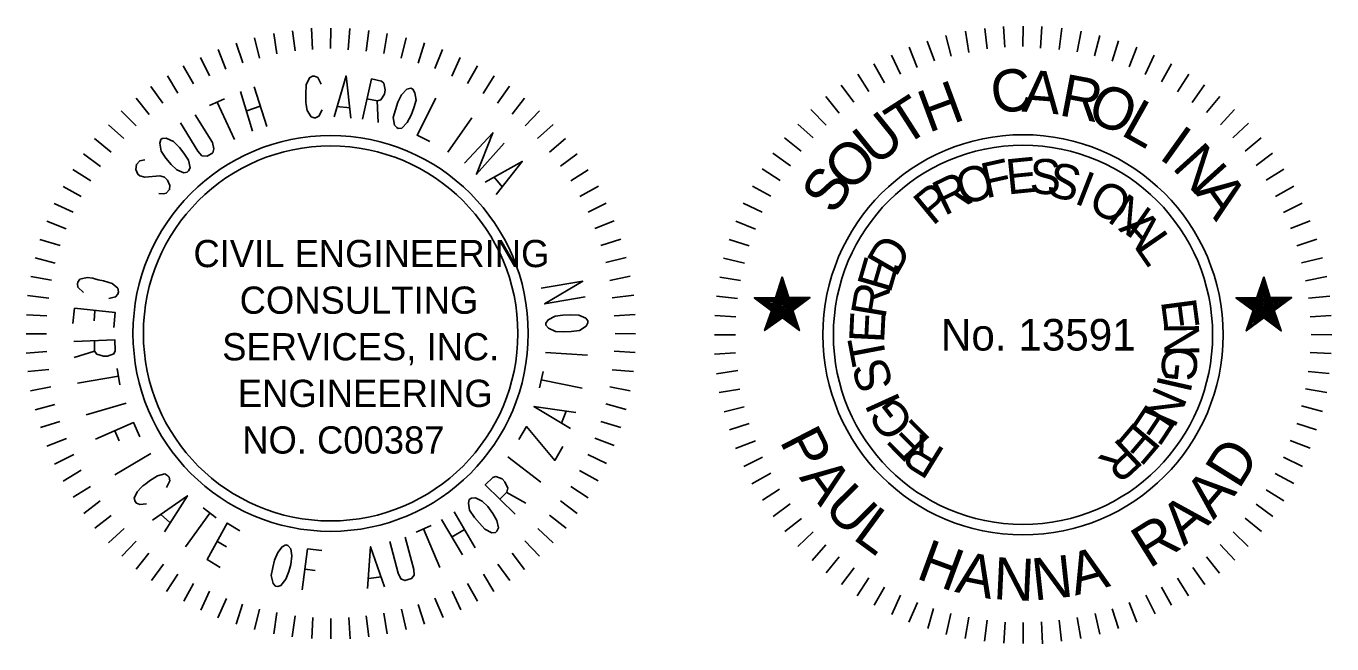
# Model space of a CAD drawing. Extents: x 116 to 2310, y 9 to 1131.
# Drawn here: x 1822.2 to 2001.5, y 103.4 to 188.2 of the extents above; entities that cross this region are included whole.
import ezdxf

# ---------------------------------------------------------------- set-up
doc = ezdxf.new("R2010")
doc.units = 0
doc.layers.add('RD_SHT_SEAL_PR', color=7, linetype='Continuous')

msp = doc.modelspace()

# ---------------------------------------------------------------- linework, layer by layer
at = {"layer": 'RD_SHT_SEAL_PR'}
for p, q in [((1853.53, 186.65), (1854.23, 183.85)), ((1856.18, 187.25), (1856.63, 184.45)), ((1858.78, 187.6), (1859.13, 184.85)), ((1861.38, 187.95), (1861.53, 185.05)), ((1864.03, 187.95), (1863.98, 185.15)), ((1866.63, 187.9), (1866.43, 185)), ((1869.23, 187.65), (1868.88, 184.8)), ((1871.78, 187.25), (1871.33, 184.5)), ((1874.38, 186.65), (1873.68, 183.85)), ((1948.48, 186.95), (1949.24, 184.13)), ((1951.18, 187.53), (1951.67, 184.62)), ((1953.83, 187.92), (1954.15, 185.1)), ((1956.42, 188.19), (1956.58, 185.33)), ((1959.12, 188.24), (1959.07, 185.43)), ((1961.66, 188.18), (1961.5, 185.22)), ((1964.42, 187.97), (1964.04, 185.05)), ((1967.06, 187.54), (1966.52, 184.73)), ((1969.65, 186.95), (1968.9, 184.14)), ((1848.58, 185.05), (1849.63, 182.35)), ((1851.03, 185.9), (1851.93, 183.2)), ((1876.88, 185.95), (1876.03, 183.15)), ((1879.38, 185.05), (1878.33, 182.4)), ((1943.46, 185.33), (1944.54, 182.57)), ((1945.94, 186.19), (1946.92, 183.49)), ((1972.19, 186.24), (1971.32, 183.43)), ((1974.73, 185.33), (1973.65, 182.63)), ((1846.13, 183.95), (1847.38, 181.4)), ((1881.78, 183.95), (1880.63, 181.35)), ((1938.6, 183.06), (1940.06, 180.46)), ((1941.03, 184.24), (1942.27, 181.65)), ((1977.1, 184.24), (1975.86, 181.6)), ((1979.48, 183.06), (1978.13, 180.57)), ((1841.58, 181.4), (1843.03, 179.05)), ((1843.73, 182.8), (1845.18, 180.3)), ((1884.18, 182.8), (1882.78, 180.35)), ((1886.48, 181.4), (1884.93, 179)), ((1936.39, 181.65), (1937.9, 179.28)), ((1981.86, 181.65), (1980.29, 179.22)), ((1839.33, 179.95), (1840.98, 177.65)), ((1888.58, 180), (1886.93, 177.65)), ((1934.12, 180.14), (1935.85, 177.82)), ((1984.02, 180.19), (1982.34, 177.76)), ((1837.28, 178.35), (1839.08, 176.1)), ((1890.63, 178.35), (1888.93, 176.15)), ((1932.02, 178.57), (1933.85, 176.3)), ((1986.12, 178.58), (1984.29, 176.36)), ((1835.23, 176.6), (1837.28, 174.55)), ((1892.68, 176.61), (1890.73, 174.55)), ((1929.96, 176.79), (1932.07, 174.63)), ((1988.12, 176.79), (1986.23, 174.68)), ((1833.48, 174.7), (1835.58, 172.8)), ((1894.58, 174.75), (1892.43, 172.8)), ((1928.18, 174.79), (1930.29, 172.9)), ((1990.06, 174.9), (1987.9, 172.9)), ((1831.59, 172.8), (1833.88, 170.95)), ((1896.28, 172.8), (1894.08, 170.95)), ((1926.34, 172.9), (1928.62, 171.07)), ((1991.79, 172.9), (1989.58, 171.07)), ((1830.08, 170.7), (1832.38, 168.95)), ((1897.88, 170.7), (1895.58, 169)), ((1924.72, 170.8), (1927.15, 169.07)), ((1993.36, 170.8), (1991.09, 169.12)), ((1923.27, 168.64), (1925.75, 167.02)), ((1994.92, 168.58), (1992.49, 167.07)), ((1828.58, 168.55), (1831.08, 167)), ((1899.38, 168.5), (1896.98, 167)), ((1827.28, 166.2), (1829.73, 164.85)), ((1900.78, 166.25), (1898.23, 164.85)), ((1921.92, 166.26), (1924.45, 164.91)), ((1996.27, 166.26), (1993.79, 164.86)), ((1826.03, 163.9), (1828.63, 162.7)), ((1901.83, 163.91), (1899.39, 162.7)), ((1920.67, 163.94), (1923.27, 162.7)), ((1997.41, 163.94), (1994.87, 162.65)), ((1825.03, 161.45), (1827.68, 160.4)), ((1902.93, 161.5), (1900.28, 160.45)), ((1919.65, 161.45), (1922.35, 160.38)), ((1998.54, 161.51), (1995.84, 160.43)), ((1824.08, 158.95), (1826.88, 158.1)), ((1903.88, 159), (1901.13, 158.1)), ((1918.73, 158.92), (1921.48, 158.05)), ((1999.46, 158.97), (1996.71, 158.05)), ((1823.43, 156.4), (1826.18, 155.7)), ((1904.58, 156.45), (1901.78, 155.8)), ((1917.97, 156.38), (1920.84, 155.68)), ((2000.22, 156.43), (1997.36, 155.73)), ((1822.83, 153.85), (1825.68, 153.35)), ((1905.13, 153.9), (1902.33, 153.3)), ((1917.44, 153.78), (1920.29, 153.3)), ((2000.81, 153.84), (1997.89, 153.25)), ((1822.38, 151.25), (1825.28, 150.9)), ((1905.63, 151.3), (1902.68, 150.95)), ((1917, 151.14), (1919.87, 150.82)), ((2001.24, 151.14), (1998.32, 150.87)), ((1822.23, 148.6), (1825.03, 148.45)), ((1905.83, 148.65), (1902.93, 148.45)), ((1916.79, 148.49), (1919.65, 148.33)), ((2001.4, 148.5), (1998.54, 148.33)), ((1822.18, 146), (1824.98, 146)), ((1905.88, 146), (1903.08, 146.05)), ((1916.73, 145.85), (1919.59, 145.85)), ((2001.51, 145.85), (1998.65, 145.9)), ((1822.18, 143.35), (1825.03, 143.55)), ((1905.83, 143.4), (1902.94, 143.6)), ((1916.73, 143.2), (1919.59, 143.37)), ((2001.41, 143.26), (1998.54, 143.42)), ((1822.43, 140.8), (1825.28, 141.1)), ((1905.58, 140.8), (1902.68, 141.05)), ((1917, 140.5), (1919.92, 140.93)), ((2001.14, 140.55), (1998.27, 140.83)), ((1822.78, 138.15), (1825.58, 138.7)), ((1905.14, 138.15), (1902.33, 138.7)), ((1917.38, 137.91), (1920.19, 138.4)), ((2000.81, 137.91), (1997.89, 138.45)), ((1823.43, 135.55), (1826.13, 136.3)), ((1904.58, 135.6), (1901.78, 136.35)), ((1918.03, 135.27), (1920.78, 135.97)), ((2000.22, 135.32), (1997.36, 136.08)), ((1824.18, 133.1), (1826.83, 133.95)), ((1903.88, 133.1), (1901.13, 133.95)), ((1918.79, 132.78), (1921.49, 133.65)), ((1999.41, 132.78), (1996.71, 133.65)), ((1825.03, 130.55), (1827.73, 131.6)), ((1902.93, 130.65), (1900.28, 131.65)), ((1919.59, 130.25), (1922.35, 131.27)), ((1998.54, 130.3), (1995.79, 131.33)), ((1826.08, 128.1), (1828.73, 129.4)), ((1901.88, 128.16), (1899.33, 129.4)), ((1920.73, 127.76), (1923.32, 129.05)), ((1997.47, 127.76), (1994.87, 129.06)), ((1827.28, 125.75), (1829.73, 127.25)), ((1900.74, 125.8), (1898.18, 127.2)), ((1921.86, 125.38), (1924.46, 126.84)), ((1996.27, 125.44), (1993.74, 126.79)), ((1828.63, 123.55), (1831.03, 125)), ((1899.38, 123.45), (1896.98, 125)), ((1923.32, 123.12), (1925.64, 124.63)), ((1994.93, 123.06), (1992.49, 124.57)), ((1830.13, 121.3), (1832.33, 123.05)), ((1897.88, 121.3), (1895.58, 123.05)), ((1924.78, 120.9), (1927.1, 122.63)), ((1993.41, 120.9), (1991.09, 122.58)), ((1831.63, 119.3), (1833.88, 121.05)), ((1896.33, 119.3), (1894.08, 121.1)), ((1926.4, 118.85), (1928.67, 120.63)), ((1991.84, 118.85), (1989.58, 120.68)), ((1833.48, 117.3), (1835.63, 119.25)), ((1894.58, 117.3), (1892.48, 119.25)), ((1928.18, 116.8), (1930.29, 118.8)), ((1990.01, 116.8), (1987.96, 118.8)), ((1835.33, 115.45), (1837.28, 117.5)), ((1892.68, 115.45), (1890.68, 117.55)), ((1930.12, 114.85), (1932.02, 117.02)), ((1988.17, 114.91), (1986.18, 117.07)), ((1837.28, 113.65), (1839.03, 115.85)), ((1890.63, 113.6), (1888.93, 115.85)), ((1932.07, 113.18), (1933.85, 115.34)), ((1986.07, 113.13), (1984.29, 115.34)), ((1839.38, 112.1), (1841.03, 114.35)), ((1841.48, 110.6), (1843.03, 113)), ((1886.43, 110.6), (1884.98, 113)), ((1888.63, 112.1), (1886.98, 114.35)), ((1934.17, 111.56), (1935.9, 113.83)), ((1984.07, 111.56), (1982.4, 113.88)), ((1843.83, 109.25), (1845.18, 111.7)), ((1884.18, 109.25), (1882.78, 111.7)), ((1936.33, 109.99), (1937.9, 112.48)), ((1981.8, 110), (1980.29, 112.43)), ((1846.18, 108.05), (1847.38, 110.65)), ((1848.53, 107), (1849.68, 109.65)), ((1879.48, 107.05), (1878.33, 109.7)), ((1881.88, 108.1), (1880.68, 110.65)), ((1938.66, 108.7), (1940.06, 111.18)), ((1941.09, 107.45), (1942.27, 110.1)), ((1977.22, 107.51), (1975.97, 110.1)), ((1979.48, 108.7), (1978.13, 111.18)), ((1851.03, 106.1), (1851.88, 108.85)), ((1853.53, 105.4), (1854.23, 108.15)), ((1856.18, 104.8), (1856.63, 107.7)), ((1871.78, 104.8), (1871.33, 107.6)), ((1874.38, 105.4), (1873.73, 108.15)), ((1876.88, 106.1), (1876.03, 108.8)), ((1943.41, 106.38), (1944.59, 109.08)), ((1946, 105.51), (1946.81, 108.27)), ((1972.19, 105.51), (1971.33, 108.21)), ((1974.73, 106.38), (1973.65, 109.08)), ((1858.73, 104.35), (1859.13, 107.25)), ((1861.43, 104.15), (1861.58, 107.05)), ((1864.03, 104.1), (1864.03, 106.9)), ((1866.68, 104.1), (1866.48, 107.05)), ((1869.23, 104.35), (1868.88, 107.25)), ((1948.54, 104.7), (1949.19, 107.56)), ((1951.13, 104.16), (1951.67, 107.08)), ((1953.78, 103.78), (1954.16, 106.65)), ((1956.48, 103.51), (1956.64, 106.38)), ((1959.12, 103.46), (1959.12, 106.32)), ((1961.77, 103.4), (1961.61, 106.43)), ((1964.36, 103.78), (1964.04, 106.65)), ((1967.01, 104.16), (1966.52, 107.02)), ((1969.65, 104.75), (1969.01, 107.57))]:
    msp.add_line(p, q, dxfattribs=at)
for points in [[(1862.69, 180.25), (1862.23, 181.2), (1861.78, 181.35), (1861.53, 181.35), (1861.08, 181.15), (1860.63, 180.2), (1860.58, 178.9), (1860.58, 178.25), (1860.58, 177.8), (1860.63, 177.45), (1860.78, 176.65), (1861.34, 175.8), (1861.73, 175.65), (1861.93, 175.65), (1862.38, 175.86), (1862.83, 176.75)], [(1864.48, 175.8), (1866.13, 181.4), (1866.78, 175.6)], [(1855.23, 174.45), (1853.48, 179.9)], [(1868.38, 175.45), (1869.63, 181), (1870.98, 180.7), (1871.33, 180.4), (1871.48, 179.5), (1871.38, 178.9), (1870.88, 178.1), (1870.43, 178), (1868.98, 178.25)], [(1875.03, 179.7), (1875.28, 179.6), (1875.58, 179.1), (1875.73, 178.05), (1875.43, 177), (1875.08, 176), (1874.53, 175), (1873.78, 174.25), (1873.28, 174.2), (1873.08, 174.3), (1872.78, 174.65), (1872.58, 175.71), (1872.93, 176.76), (1873.23, 177.8), (1873.73, 178.8), (1874.48, 179.6), (1875.03, 179.7)], [(1847.38, 177.35), (1849.43, 178.25)], [(1848.43, 177.8), (1850.78, 172.65)], [(1851.63, 179.25), (1853.28, 173.8)], [(1870.38, 178), (1870.53, 175)], [(1878.43, 178.36), (1875.88, 173.25), (1877.63, 172.4)], [(1843.38, 174.95), (1845.78, 171.05), (1846.33, 170.45), (1847.03, 170.4), (1847.83, 170.85), (1847.98, 171.4), (1847.78, 172.25), (1845.38, 176.05)], [(1854.33, 177.25), (1852.48, 176.6)], [(1866.68, 177), (1864.83, 177.2)], [(1880.08, 170.95), (1883.38, 175.65)], [(1840.68, 172.65), (1840.88, 172.8), (1841.43, 172.85), (1842.43, 172.4), (1843.23, 171.55), (1843.83, 170.8), (1844.48, 169.85), (1844.73, 168.8), (1844.48, 168.35), (1844.28, 168.2), (1843.83, 168.1), (1842.88, 168.5), (1842.08, 169.25), (1841.38, 170.1), (1840.73, 171.05), (1840.53, 172.15), (1840.68, 172.65)], [(1882.38, 169.4), (1886.28, 173.6), (1884.03, 167.9), (1887.83, 172.15)], [(1838.48, 169.9), (1837.78, 169.75), (1837.33, 169.25), (1837.23, 168.55), (1837.53, 167.9), (1837.78, 167.7), (1838.48, 167.5), (1840.53, 167.7), (1841.18, 167.5), (1841.58, 167.1), (1841.93, 166.35), (1841.88, 165.8), (1841.43, 165.3), (1841.03, 165.2), (1840.43, 165.25)], [(1885.23, 166.8), (1890.33, 169.65), (1886.73, 165.1)], [(1887.58, 166.15), (1886.48, 167.5)], [(1833.53, 150.85), (1834.48, 151.05), (1834.78, 151.45), (1834.88, 151.75), (1834.78, 152.25), (1833.98, 152.9), (1832.83, 153.25), (1832.08, 153.4), (1831.63, 153.55), (1831.33, 153.65), (1830.58, 153.7), (1829.58, 153.5), (1829.28, 153.1), (1829.23, 152.85), (1829.28, 152.4), (1830.08, 151.65)], [(1898.98, 151.05), (1893.38, 150.1), (1898.63, 153.2), (1892.93, 152.25)], [(1834.23, 146.85), (1834.43, 148.9), (1828.83, 149.5), (1828.58, 147.4)], [(1831.63, 149.15), (1831.53, 147.75)], [(1893.58, 147.16), (1893.58, 147.45), (1893.88, 147.9), (1894.83, 148.4), (1895.88, 148.55), (1896.98, 148.6), (1898.08, 148.55), (1899.03, 148.15), (1899.33, 147.75), (1899.33, 147.5), (1899.08, 147.05), (1898.18, 146.45), (1897.03, 146.3), (1896.03, 146.25), (1894.88, 146.3), (1893.93, 146.75), (1893.58, 147.16)], [(1828.73, 144.95), (1834.38, 145.15), (1834.43, 143.65), (1834.23, 143.25), (1833.38, 142.9), (1832.83, 142.9), (1831.88, 143.2), (1831.58, 143.6), (1831.58, 145)], [(1831.58, 143.6), (1828.78, 142.75)], [(1899.28, 143.05), (1893.53, 143.4)], [(1834.88, 140.15), (1829.23, 139.2)], [(1834.68, 141.2), (1835.03, 139)], [(1892.68, 138.56), (1893.18, 140.8)], [(1892.93, 139.65), (1898.53, 138.5)], [(1830.43, 134.85), (1835.93, 136.45)], [(1896.93, 133), (1891.93, 136), (1897.68, 135.2)], [(1896.33, 135.35), (1895.73, 133.7)], [(1837.79, 131.85), (1836.93, 133.8), (1831.73, 131.5)], [(1889.83, 131.45), (1890.88, 133.25), (1894.78, 128.6), (1895.88, 130.5)], [(1834.38, 132.65), (1834.98, 131.3)], [(1834.38, 126.6), (1839.33, 129.55)], [(1892.88, 125.6), (1888.33, 129.1)], [(1841.48, 124.9), (1841.93, 125.8), (1841.83, 126.3), (1841.63, 126.5), (1841.23, 126.75), (1840.23, 126.5), (1839.13, 125.8), (1838.63, 125.4), (1838.23, 125.1), (1837.98, 124.9), (1837.43, 124.3), (1837.03, 123.4), (1837.18, 122.95), (1837.33, 122.75), (1837.78, 122.55), (1838.73, 122.65)], [(1889.33, 121.2), (1885.23, 125.25), (1886.28, 126.25), (1886.68, 126.4), (1887.58, 126.05), (1887.93, 125.65), (1888.33, 124.8), (1888.18, 124.25), (1887.23, 123.3)], [(1839.53, 120.4), (1844.33, 123.75), (1841.18, 118.8)], [(1888.13, 124.25), (1890.83, 122.75)], [(1846.48, 122.1), (1848.28, 120.7)], [(1883.03, 123.25), (1883.33, 123.4), (1883.89, 123.45), (1884.83, 123), (1885.58, 122.25), (1886.28, 121.3), (1886.83, 120.35), (1887.08, 119.35), (1886.83, 118.9), (1886.63, 118.7), (1886.13, 118.65), (1885.18, 119.15), (1884.43, 120), (1883.78, 120.75), (1883.08, 121.75), (1882.93, 122.75), (1883.03, 123.25)], [(1841.93, 120.06), (1840.63, 121.2)], [(1847.43, 121.35), (1844.08, 116.75)], [(1879.23, 120.5), (1882.13, 115.65)], [(1883.83, 116.6), (1880.98, 121.55)], [(1851.53, 118.95), (1849.78, 120), (1847.04, 115), (1848.83, 113.9)], [(1875.73, 118.75), (1877.83, 119.65)], [(1876.78, 119.2), (1878.98, 113.9)], [(1882.38, 119.1), (1880.68, 118.1)], [(1848.38, 117.5), (1849.68, 116.75)], [(1857.83, 117), (1858.13, 116.9), (1858.53, 116.45), (1858.68, 115.5), (1858.53, 114.31), (1858.28, 113.35), (1857.83, 112.3), (1857.18, 111.4), (1856.73, 111.3), (1856.43, 111.35), (1856.13, 111.7), (1855.83, 112.8), (1856.08, 113.9), (1856.28, 114.9), (1856.73, 115.95), (1857.33, 116.75), (1857.83, 117)], [(1869.08, 111), (1869.48, 116.75), (1871.38, 111.25)], [(1872.13, 117.45), (1873.28, 113.1), (1873.63, 112.35), (1874.18, 112.1), (1875.13, 112.4), (1875.48, 112.85), (1875.43, 113.6), (1874.23, 118.05)], [(1862.78, 116.25), (1860.83, 116.45), (1860.08, 110.85)], [(1860.48, 113.65), (1861.88, 113.5)], [(1870.93, 112.6), (1869.23, 112.4)]]:
    msp.add_lwpolyline(points, dxfattribs=at)
for points in [[(1926.02, 153.79), (1925.1, 150.93), (1922.19, 150.93), (1924.56, 149.14), (1923.59, 146.44), (1926.07, 148.17), (1928.39, 146.44), (1927.48, 149.2), (1929.86, 150.98), (1926.94, 150.98)], [(1925.97, 153.35), (1925.21, 150.87), (1922.51, 150.87), (1924.62, 149.25), (1923.86, 146.71), (1925.97, 148.33), (1928.12, 146.71), (1927.32, 149.3), (1929.53, 150.82), (1926.88, 150.87)], [(1926.07, 152.98), (1925.21, 150.71), (1922.89, 150.71), (1924.83, 149.3), (1924.13, 147.04), (1926.02, 148.44), (1927.97, 146.98), (1927.15, 149.36), (1929.15, 150.65), (1926.77, 150.71)], [(1926.07, 152.6), (1925.32, 150.6), (1923.27, 150.55), (1924.99, 149.36), (1924.34, 147.36), (1925.97, 148.6), (1927.75, 147.36), (1927.15, 149.36), (1928.77, 150.65), (1926.67, 150.55)], [(1992.17, 153.79), (1991.2, 150.98), (1988.34, 150.93), (1990.71, 149.2), (1989.74, 146.39), (1992.17, 148.17), (1994.55, 146.39), (1993.57, 149.2), (1996, 150.98), (1993.04, 150.98)], [(1992.12, 153.41), (1991.31, 150.87), (1988.66, 150.82), (1990.87, 149.2), (1990.07, 146.71), (1992.17, 148.23), (1994.33, 146.71), (1993.52, 149.25), (1995.68, 150.87), (1992.98, 150.82)], [(1992.17, 152.98), (1991.47, 150.65), (1989.04, 150.71), (1990.98, 149.3), (1990.28, 146.98), (1992.17, 148.44), (1994.12, 147.04), (1993.36, 149.25), (1995.3, 150.76), (1992.93, 150.71)], [(1992.12, 152.6), (1991.52, 150.55), (1989.42, 150.55), (1991.2, 149.36), (1990.39, 147.41), (1992.17, 148.6), (1993.84, 147.42), (1993.19, 149.36), (1994.92, 150.6), (1992.82, 150.6)], [(1926.02, 152.22), (1925.48, 150.49), (1923.64, 150.44), (1925.1, 149.41), (1924.51, 147.63), (1926.02, 148.77), (1927.53, 147.63), (1926.94, 149.41), (1928.34, 150.49), (1926.67, 150.5)], [(1926.02, 151.85), (1925.59, 150.33), (1924.02, 150.39), (1925.27, 149.47), (1924.78, 148.01), (1926.07, 148.93), (1927.32, 147.95), (1926.78, 149.47), (1928.07, 150.28), (1926.51, 150.33)], [(1926.02, 151.41), (1925.64, 150.28), (1924.4, 150.11), (1925.43, 149.52), (1925.05, 148.33), (1925.97, 149.03), (1927.1, 148.28), (1926.72, 149.52), (1927.64, 150.23), (1926.4, 150.23)], [(1926.02, 151.03), (1925.75, 150.12), (1924.78, 150.11), (1925.59, 149.58), (1925.27, 148.66), (1926.02, 149.15), (1926.83, 148.6), (1926.56, 149.52), (1927.32, 150.06), (1926.29, 150.17)], [(1992.12, 152.17), (1991.58, 150.44), (1989.74, 150.5), (1991.2, 149.47), (1990.71, 147.63), (1992.12, 148.71), (1993.57, 147.68), (1993.09, 149.36), (1994.6, 150.44), (1992.71, 150.49)], [(1992.22, 151.79), (1991.69, 150.38), (1990.12, 150.38), (1991.42, 149.52), (1990.87, 147.95), (1992.17, 148.88), (1993.36, 148.01), (1992.98, 149.42), (1994.12, 150.33), (1992.66, 150.39)], [(1992.17, 151.41), (1991.74, 150.28), (1990.49, 150.23), (1991.57, 149.47), (1991.14, 148.33), (1992.17, 149.09), (1993.14, 148.28), (1992.76, 149.52), (1993.84, 150.23), (1992.55, 150.28)], [(1992.17, 150.98), (1991.9, 150.12), (1990.87, 150.12), (1991.68, 149.52), (1991.36, 148.66), (1992.17, 149.14), (1992.93, 148.6), (1992.66, 149.52), (1993.36, 150.11), (1992.44, 150.12)], [(1992.17, 150.65), (1991.84, 150), (1991.31, 149.95), (1991.79, 149.63), (1991.57, 148.98), (1992.17, 149.3), (1992.71, 148.93), (1992.49, 149.52), (1993.09, 149.95), (1992.44, 150.01)], [(1926.02, 150.6), (1925.8, 150.01), (1925.1, 150.01), (1925.64, 149.58), (1925.54, 148.98), (1926.07, 149.36), (1926.51, 148.93), (1926.4, 149.58), (1926.94, 149.95), (1926.24, 150.01)], [(1926.07, 150.28), (1925.86, 149.9), (1925.53, 149.9), (1925.86, 149.63), (1925.69, 149.25), (1926.07, 149.52), (1926.29, 149.25), (1926.19, 149.68), (1926.51, 149.84), (1926.18, 149.85)], [(1926.07, 149.84), (1926.02, 149.68), (1925.81, 149.74), (1925.97, 149.74), (1925.92, 149.58), (1926.02, 149.58), (1926.08, 149.58), (1926.07, 149.68), (1926.24, 149.79), (1926.07, 149.79)], [(1992.12, 150.28), (1992.07, 149.9), (1991.63, 149.9), (1992.01, 149.63), (1991.79, 149.25), (1992.22, 149.47), (1992.49, 149.25), (1992.33, 149.58), (1992.71, 149.9), (1992.33, 149.84)], [(1992.22, 149.85), (1992.17, 149.74), (1992.01, 149.74), (1992.06, 149.68), (1992.07, 149.52), (1992.12, 149.63), (1992.28, 149.63), (1992.22, 149.68), (1992.28, 149.74), (1992.17, 149.68)]]:
    msp.add_lwpolyline(points, close=True, dxfattribs=at)
for radius in [27.48, 26.04]:
    msp.add_circle((1959.09, 145.85), radius, dxfattribs=at)
for major_axis in [(0, 27.18), (0, 25.75)]:
    msp.add_ellipse((1864, 146.04), major_axis=major_axis, ratio=0.998589, dxfattribs=at)

# ---------------------------------------------------------------- texts
for s, height, rotation, p in [('C', 5.79, 7.9045, (1955.07, 176.14)), ('A', 5.79, 355.5041, (1958.85, 176.52)), ('R', 5.79, 349.3039, (1963.87, 176.03)), ('H', 5.79, 20.3049, (1946.11, 173.55)), ('O', 5.79, 336.9035, (1967.6, 175.44)), ('T', 5.79, 32.7054, (1942.71, 171.61)), ('L', 5.79, 330.7033, (1972.35, 173.39)), ('U', 5.79, 38.9056, (1938.82, 168.85)), ('I', 5.79, 324.5031, (1977.59, 170.15)), ('O', 5.79, 45.1058, (1935.31, 165.23)), ('N', 5.79, 312.1026, (1979.43, 168.8)), ('S', 5.79, 57.5062, (1933.2, 162.15)), ('O', 4.82, 19.3187, (1950.88, 163.5)), ('F', 4.82, 12.5331, (1953.97, 164.57)), ('E', 4.82, 5.7476, (1956.98, 165.11)), ('S', 4.82, 358.962, (1959.97, 165.21)), ('S', 4.82, 345.3909, (1962.09, 165.09)), ('R', 4.82, 26.1042, (1948.28, 162.13)), ('I', 4.82, 338.6054, (1965.95, 163.97)), ('O', 4.82, 331.8198, (1967.76, 163.19)), ('A', 5.79, 305.9024, (1982.61, 165.45)), ('P', 4.82, 39.6753, (1946.67, 160.72)), ('N', 4.82, 325.0343, (1970.49, 161.52)), ('A', 4.82, 311.4632, (1972.11, 160.38)), ('L', 4.82, 304.6776, (1974.33, 157.88)), ('CIVIL ENGINEERING', 3.738, 0.0016, (1845.16, 155.14)), ('D', 4.82, 60.0967, (1941.62, 153.63)), ('E', 4.82, 73.6728, (1940.87, 151.41)), ('CONSULTING', 3.738, 0.0016, (1851.51, 148.74)), ('R', 4.82, 80.4609, (1940.17, 147.95)), ('E', 4.82, 277.5354, (1978.02, 150.49)), ('E', 4.82, 87.249, (1940.01, 144.66)), ('No. 13591', 4.336, 0.0004, (1947.81, 143.69)), ('SERVICES, INC.', 3.738, 0.0016, (1849.11, 142.34)), ('N', 4.82, 270.7499, (1978.45, 147.51)), ('T', 4.82, 100.8252, (1940.44, 142.18)), ('G', 4.82, 263.9643, (1978.44, 144.52)), ('S', 4.82, 107.6133, (1941.36, 138.88)), ('I', 4.82, 257.1788, (1977.74, 140.49)), ('ENGINEERING', 3.738, 0.0016, (1851.26, 135.94)), ('N', 4.82, 246.8176, (1977.31, 139.05)), ('I', 4.82, 114.4014, (1942.38, 136.67)), ('G', 4.82, 127.9775, (1944.38, 133.81)), ('E', 4.82, 236.4563, (1976.23, 136.64)), ('NO. C00387', 3.738, 0.0016, (1851.86, 129.54)), ('P', 5.78, 297.3177, (1925.59, 131.26)), ('E', 4.82, 134.7656, (1946.59, 131.43)), ('E', 4.82, 229.6708, (1974.52, 134.09)), ('R', 4.82, 148.3418, (1948.59, 129.98)), ('R', 4.82, 222.8852, (1972.52, 131.87)), ('D', 5.78, 58.0167, (1988.74, 124.5)), ('A', 5.78, 306.2426, (1928.26, 126.24)), ('U', 5.78, 314.7425, (1931.5, 121.89)), ('A', 5.78, 49.5168, (1985.26, 120.35)), ('L', 5.78, 323.6675, (1935.55, 117.9)), ('A', 5.78, 41.0169, (1981.2, 116.76)), ('R', 5.78, 32.0919, (1976.42, 113.68)), ('H', 5.78, 339.8173, (1944.25, 112.46)), ('A', 5.78, 348.7423, (1949.61, 110.56)), ('N', 5.78, 357.2422, (1954.93, 109.55)), ('N', 5.78, 6.1671, (1960.61, 109.34)), ('A', 5.78, 15.0921, (1966.26, 110.02))]:
    msp.add_text(s, height=height, rotation=rotation, dxfattribs=at).set_placement(p)

doc.saveas('drawing.dxf')
